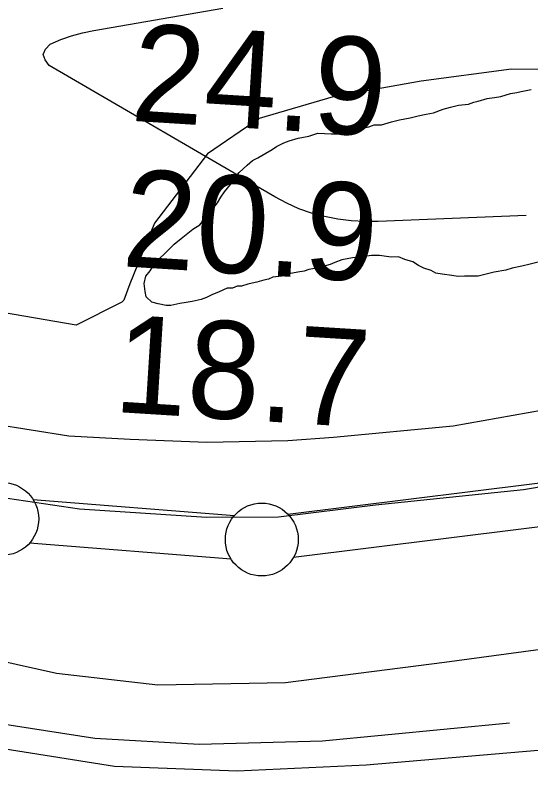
# Model space of a CAD drawing. Extents: x 3405885 to 3443815, y 558517 to 583997.
# Drawn here: x 3422635 to 3422989, y 566462 to 566980 of the extents above; entities that cross this region are included whole.
import ezdxf

# ---------------------------------------------------------------- set-up
doc = ezdxf.new("R2010")
doc.units = 0
for name, color, linetype in [('V-FLOD-BASE', 7, 'Continuous'), ('V-LEVE-TOET', 7, 'Continuous'), ('V-RIVR-RANG', 7, 'Continuous'), ('V-ROAD-CNTR', 7, 'Continuous'), ('V-SITE-VEGE', 7, 'Continuous'), ('V-SURV-LINE', 7, 'Continuous'), ('V-TOPO-MINR', 7, 'Continuous'), ('V-TOPO-SHOR', 7, 'Continuous')]:
    doc.layers.add(name, color=color, linetype=linetype)

msp = doc.modelspace()

# ---------------------------------------------------------------- linework, layer by layer
at = {"layer": 'V-FLOD-BASE'}
msp.add_lwpolyline([(3422154.33, 566745.94), (3422288.27, 566718.27), (3422391.8, 566698.04), (3422520.81, 566669.67), (3422623.11, 566649.42), (3422678.86, 566641.23), (3422766.05, 566635.52), (3422815.45, 566635.85), (3422882, 566643.94), (3422983.7, 566654.56), (3423092.05, 566672.72), (3423194.72, 566696.94), (3423294.3, 566721.11), (3423428.35, 566751.5), (3423559.31, 566781.83), (3423729.02, 566820.95), (3423863.03, 566853.19), (3424026.56, 566892.19), (3424213.56, 566931.02), (3424372.21, 566966.83)], dxfattribs=at)
at = {"layer": 'V-LEVE-TOET'}
for points in [[(3423260.2, 566759.98), (3423217.12, 566751.73), (3423158.11, 566737.61), (3423098.45, 566724.72), (3423048.55, 566718.2), (3422935.3, 566698.09), (3422853.31, 566690.32), (3422821.86, 566687.86), (3422766.29, 566686.78), (3422713.75, 566688.85), (3422671.71, 566691.12), (3422619.67, 566699.38), (3422558.93, 566710.55), (3422507.47, 566720.67), (3422437.36, 566737.22), (3422322.74, 566756), (3422186.98, 566781.78)], [(3423055.69, 566547.63), (3423042.63, 566548.19), (3423026.02, 566548.9), (3422929.3, 566535.91), (3422820.25, 566522.06), (3422732.59, 566520.36), (3422663.26, 566528.28), (3422582, 566546.47), (3422466.7, 566568.32), (3422368.78, 566585.56), (3422281.25, 566608.57), (3422157.81, 566636.44)]]:
    msp.add_lwpolyline(points, dxfattribs=at)
at = {"layer": 'V-ROAD-CNTR'}
msp.add_lwpolyline([(3422060.19, 566587.38), (3422266.86, 566545.23), (3422516.76, 566494.36), (3422702.93, 566464.71), (3422787.21, 566461.56), (3422875.59, 566465.75), (3422993.61, 566475.82), (3423128.36, 566504.48), (3423290.21, 566543.77), (3423675.18, 566635.18), (3423909.45, 566692.29), (3424008.78, 566718.08), (3424139.12, 566759.8), (3424256.49, 566798.13), (3424350.8, 566826.7), (3424433.28, 566847.34)], dxfattribs=at)
at = {"layer": 'V-SITE-VEGE'}
msp.add_lwpolyline([(3423233.57, 566862.2), (3423172.21, 566825.14), (3423157.09, 566822.08), (3423157.01, 566826.22), (3423179.97, 566851.5), (3423208.24, 566887.92), (3423215.95, 566917.04), (3423210.06, 566936.24), (3423193.3, 566946.95), (3423150.36, 566955.78), (3423103.39, 566959), (3423067.67, 566951.41), (3423038.87, 566942.57), (3422975.4, 566942.72), (3422913.47, 566934.62), (3422852.98, 566923.79), (3422802.22, 566909.01), (3422766.82, 566884.87), (3422730.49, 566837.26), (3422713.37, 566795.54), (3422709.44, 566784.43), (3422708.09, 566783.02), (3422676.67, 566767.24), (3422431.66, 566809.39)], dxfattribs=at)
at = {"layer": 'V-SURV-LINE'}
for points in [[(3422821.99, 566637.59), (3423031.55, 566663.69)], [(3422647.02, 566647.75), (3422785.29, 566636.76)], [(3423035.27, 566633.93), (3422825.71, 566607.82)], [(3422782.92, 566606.86), (3422644.65, 566617.84)]]:
    msp.add_lwpolyline(points, dxfattribs=at)
for centre in [(3422625.93, 566634.37), (3422804.01, 566620.23)]:
    msp.add_circle(centre, 25, dxfattribs=at)
at = {"layer": 'V-TOPO-MINR'}
msp.add_lwpolyline([(3422985.38, 566842.37), (3422883.97, 566838.33), (3422874.69, 566838.32), (3422865.46, 566838.8), (3422856.29, 566840.01), (3422847.17, 566841.7), (3422838.24, 566844.16), (3422829.51, 566847.14), (3422821.1, 566850.91), (3422812.89, 566855.2), (3422658.21, 566945.32), (3422655.27, 566949.13), (3422654.1, 566952.86), (3422655.59, 566956.47), (3422658.86, 566960), (3422666.1, 566963.06), (3422673.47, 566965.71), (3422681.03, 566967.76), (3422688.71, 566969.4), (3422777.18, 566984.6)], dxfattribs=at)
at = {"layer": 'V-TOPO-SHOR'}
for points in [[(3422851.7, 566898.45), (3422856.02, 566898.53), (3422859.72, 566899.22), (3422867.08, 566901.83), (3422870.17, 566901.89), (3422877.55, 566903.27), (3422881.23, 566904.58), (3422886.18, 566904.68), (3422892.93, 566906.66), (3422898.46, 566908), (3422905.85, 566909.38), (3422911.38, 566910.72), (3422916.92, 566912.07), (3422921.84, 566912.78), (3422928.59, 566915.38), (3422933.5, 566916.71), (3422939.04, 566918.06), (3422945.82, 566918.8), (3422949.5, 566920.11), (3422952.57, 566920.79), (3422958.71, 566922.76), (3422963.64, 566923.47), (3422967.95, 566924.17), (3422974.71, 566926.16), (3422979.02, 566926.86), (3422982.09, 566927.54), (3422988.86, 566928.91)], [(3422819.08, 566892.26), (3422822.77, 566893.56), (3422828.91, 566895.54), (3422832.6, 566896.22), (3422836.29, 566896.91), (3422842.43, 566898.89), (3422851.7, 566898.45)], [(3422993.63, 566810.4), (3422988.1, 566809.05), (3422982.56, 566807.71), (3422975.8, 566806.35), (3422971.5, 566805.03), (3422963.49, 566803.64), (3422957.96, 566802.29), (3422952.43, 566800.95), (3422943.17, 566800.77), (3422938.84, 566800.69), (3422934.51, 566801.22), (3422927.69, 566802.32), (3422923.36, 566802.86), (3422920.23, 566804.65), (3422915.26, 566806.41), (3422911.52, 566808.19), (3422907.77, 566810.59), (3422902.17, 566812.33), (3422897.81, 566814.1), (3422892.88, 566814), (3422884.82, 566815.08), (3422879.27, 566814.97), (3422874.34, 566814.26), (3422866.33, 566813.49), (3422862.63, 566812.8), (3422858.94, 566812.11), (3422854.04, 566810.16), (3422850.97, 566808.87), (3422843.6, 566806.87), (3422840.52, 566806.19), (3422836.21, 566805.49), (3422833.15, 566804.2), (3422828.84, 566803.5), (3422821.45, 566802.12), (3422817.77, 566800.81), (3422811.61, 566800.07), (3422808.54, 566798.78), (3422805.47, 566798.1), (3422800.55, 566796.77), (3422797.48, 566796.09), (3422794.4, 566795.42), (3422790.1, 566794.1), (3422787.02, 566794.04), (3422783.95, 566792.74), (3422780.25, 566792.67), (3422774.74, 566790.09), (3422769.83, 566788.14), (3422766.17, 566786.22), (3422762.48, 566784.91), (3422756.33, 566783.56), (3422752.02, 566782.86), (3422747.71, 566782.16), (3422741.56, 566780.8), (3422738.48, 566780.74), (3422732.9, 566781.87), (3422728.55, 566783.02), (3422724.77, 566786.65), (3422724.08, 566790.35), (3422723.36, 566795.89), (3422724.5, 566800.85), (3422727.51, 566804.62), (3422730.5, 566809.62), (3422733.53, 566812.77), (3422737.78, 566816.55), (3422743.84, 566822.85), (3422748.7, 566826.65), (3422756.61, 566832.98), (3422761.49, 566836.16), (3422765.11, 566840.56), (3422768.73, 566844.95), (3422773.55, 566851.22), (3422775.95, 566854.97), (3422778.35, 566858.73), (3422782.58, 566863.75), (3422785.58, 566868.13), (3422788.6, 566871.9), (3422794.06, 566876.95), (3422797.7, 566880.1), (3422801.37, 566882.03), (3422806.87, 566885.22), (3422811.14, 566887.78), (3422814.2, 566889.69), (3422819.08, 566892.26)], [(3422973.93, 566494.24), (3422845.69, 566481.87), (3422761.1, 566479.61), (3422689.37, 566483.78), (3422611.3, 566495.85), (3422509.14, 566521.05), (3422410.78, 566541.26), (3422333.21, 566559.15), (3422113.57, 566602.95), (3421927.78, 566659.26), (3421822.97, 566680.7), (3421726.9, 566697.37), (3421687.89, 566702.17), (3421672.57, 566696.32), (3421653.48, 566692.86), (3421629.29, 566697.95), (3421516.88, 566723.07), (3421441.79, 566747.07), (3421402.46, 566755.57), (3421356.38, 566768.51)]]:
    msp.add_lwpolyline(points, dxfattribs=at)

# ---------------------------------------------------------------- texts
at = {"layer": 'V-RIVR-RANG'}
for s, p in [('24.9', (3422713.43, 566907.48)), ('20.9', (3422707.43, 566807.66)), ('18.7', (3422701.7, 566707.83))]:
    msp.add_text(s, height=67, rotation=356.4183, dxfattribs=at).set_placement(p)

doc.saveas('drawing.dxf')
